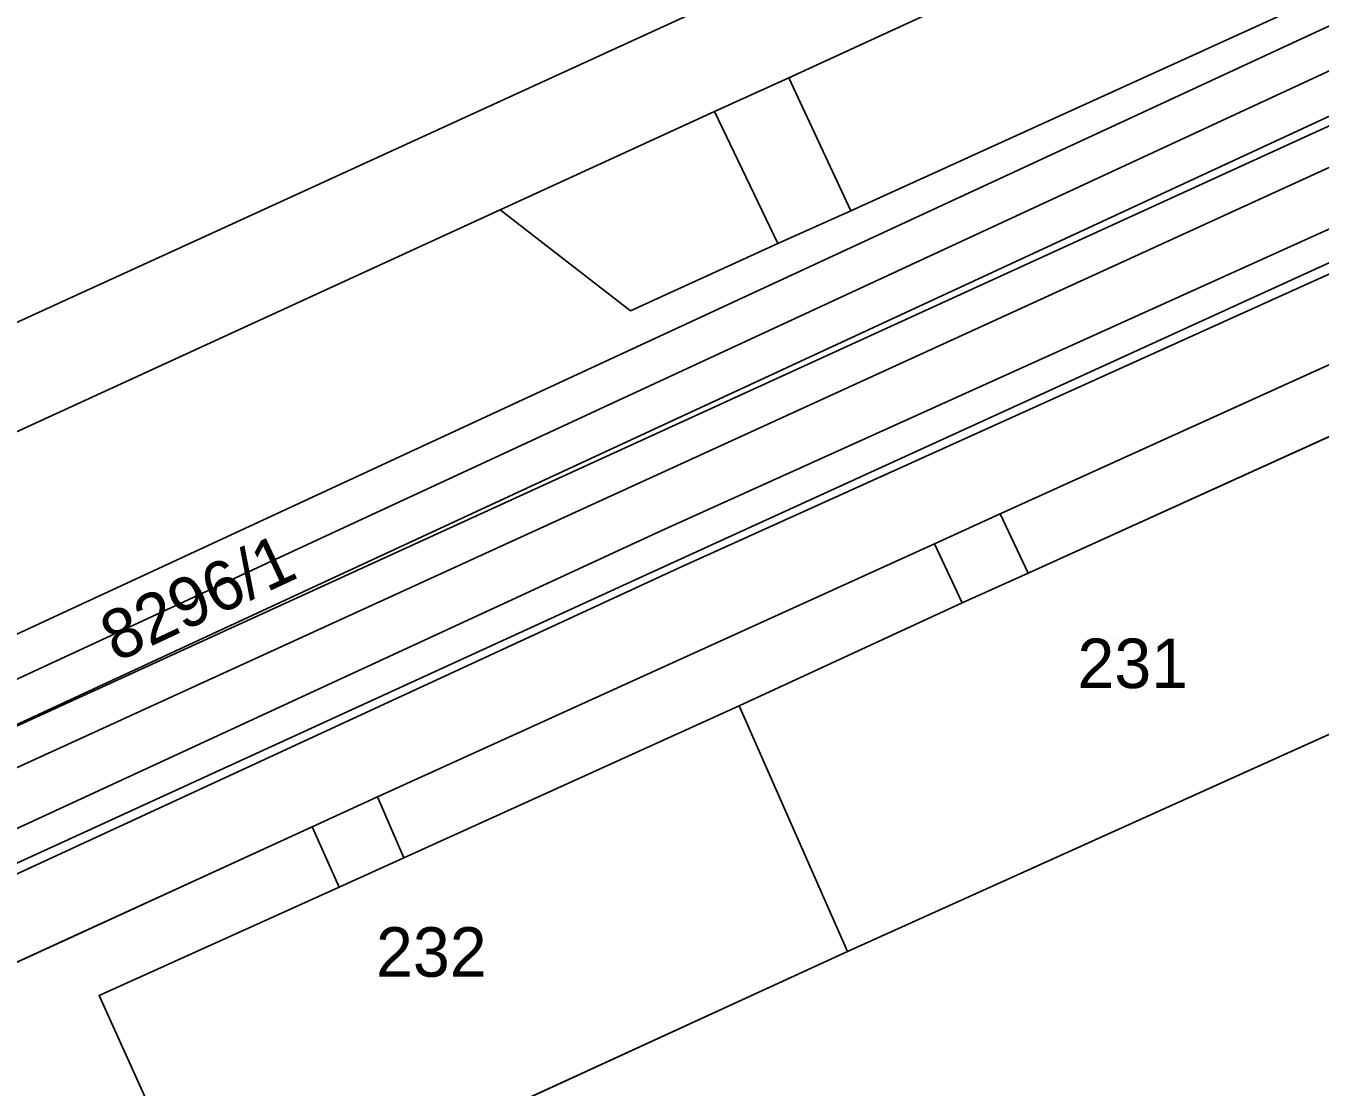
# Model space of a CAD drawing. Extents: x -264070 to -262271, y -1238894 to -1238141.
# Drawn here: x -263532.4 to -263480.2, y -1238438.9 to -1238396.1 of the extents above; entities that cross this region are included whole.
import ezdxf

# ---------------------------------------------------------------- set-up
doc = ezdxf.new("R2010")
doc.units = 0
for name, color, linetype in [('body_kn', 7, 'Continuous'), ('katuz_linie', 7, 'Continuous'), ('kladpar_druhypozemkov', 7, 'Continuous'), ('kladpar_hranice', 7, 'Continuous'), ('kladpar_parcelnecisla', 7, 'Continuous'), ('kladpar_plochy', 7, 'Continuous'), ('tarchy_linie', 7, 'Continuous'), ('zappar_hrandruhpozemk', 7, 'Continuous'), ('zuob_linie', 7, 'Continuous'), ('zuob_plochy', 7, 'Continuous')]:
    doc.layers.add(name, color=color, linetype=linetype)

msp = doc.modelspace()

# ---------------------------------------------------------------- linework, layer by layer
at = {"layer": 'body_kn'}
for p, q in [((-263501.63, -1238398.17), (-263501.63, -1238398.17)), ((-263504.63, -1238399.53), (-263504.63, -1238399.53)), ((-263504.63, -1238399.53), (-263504.63, -1238399.53)), ((-263513.28, -1238403.5), (-263513.28, -1238403.5)), ((-263499.13, -1238403.54), (-263499.13, -1238403.54)), ((-263499.13, -1238403.54), (-263499.13, -1238403.54)), ((-263524.87, -1238404.43), (-263524.87, -1238404.43)), ((-263502.07, -1238404.86), (-263502.07, -1238404.86)), ((-263508.02, -1238407.57), (-263508.02, -1238407.57)), ((-263493.11, -1238415.76), (-263493.11, -1238415.76)), ((-263493.11, -1238415.76), (-263493.11, -1238415.76)), ((-263506.75, -1238416.44), (-263506.75, -1238416.44)), ((-263495.75, -1238416.97), (-263495.75, -1238416.97)), ((-263495.75, -1238416.97), (-263495.75, -1238416.97)), ((-263506.06, -1238417.94), (-263506.06, -1238417.94)), ((-263507.21, -1238418.15), (-263507.21, -1238418.15)), ((-263491.98, -1238418.16), (-263491.98, -1238418.16)), ((-263494.64, -1238419.36), (-263494.64, -1238419.36)), ((-263503.63, -1238423.51), (-263503.63, -1238423.51)), ((-263518.23, -1238427.19), (-263518.23, -1238427.19)), ((-263518.23, -1238427.19), (-263518.23, -1238427.19)), ((-263520.86, -1238428.4), (-263520.86, -1238428.4)), ((-263520.86, -1238428.4), (-263520.86, -1238428.4)), ((-263517.17, -1238429.65), (-263517.17, -1238429.65)), ((-263517.17, -1238429.65), (-263517.17, -1238429.65)), ((-263519.77, -1238430.84), (-263519.77, -1238430.84)), ((-263499.27, -1238433.43), (-263499.27, -1238433.43)), ((-263529.46, -1238435.2), (-263529.46, -1238435.2))]:
    msp.add_line(p, q, dxfattribs=at)
at = {"layer": 'katuz_linie'}
msp.add_lwpolyline([(-263622.11, -1238448.88), (-263524.87, -1238404.43), (-263502.54, -1238394.19), (-263468.52, -1238378.6), (-263467.05, -1238377.92), (-263464.65, -1238376.78), (-263460.69, -1238376.7), (-263450.55, -1238372.11), (-263449.05, -1238375.25), (-263448.24, -1238376.95), (-263444.79, -1238375.86), (-263433.14, -1238370.43), (-263430.29, -1238369.1), (-263427.85, -1238367.96), (-263393.36, -1238351.8)], dxfattribs=at)
at = {"layer": 'kladpar_druhypozemkov'}
for p, q in [((-263525.79, -1238417.32), (-263525.79, -1238417.32)), ((-263488.36, -1238420.85), (-263488.36, -1238420.85)), ((-263516.11, -1238432.8), (-263516.11, -1238432.8))]:
    msp.add_line(p, q, dxfattribs=at)
at = {"layer": 'kladpar_hranice'}
msp.add_line((-263495.75, -1238416.97), (-263493.11, -1238415.76), dxfattribs=at)
for points in [[(-263622.11, -1238448.88), (-263524.87, -1238404.43), (-263502.54, -1238394.19), (-263468.52, -1238378.6), (-263467.05, -1238377.92), (-263464.65, -1238376.78), (-263460.69, -1238376.7), (-263450.55, -1238372.11), (-263449.05, -1238375.25), (-263448.24, -1238376.95), (-263447.6, -1238377.58), (-263446.38, -1238378.21), (-263445.22, -1238378.56), (-263432.12, -1238372.59), (-263370.5, -1238344.51)], [(-263393.39, -1238373.8), (-263400.64, -1238377.05), (-263402.96, -1238378.11), (-263409.73, -1238381.24), (-263417.07, -1238384.49), (-263419.5, -1238385.56), (-263426.69, -1238388.84), (-263428.02, -1238386.05), (-263431.45, -1238387.66), (-263438.05, -1238390.73), (-263440.52, -1238391.82), (-263451.66, -1238396.9), (-263468.15, -1238404.43), (-263470.58, -1238405.55), (-263493.11, -1238415.76), (-263495.75, -1238416.97), (-263518.23, -1238427.19), (-263520.86, -1238428.4), (-263537.75, -1238436.14)], [(-263493.11, -1238415.76), (-263470.58, -1238405.55), (-263468.15, -1238404.43), (-263451.66, -1238396.9), (-263450.61, -1238399.35), (-263426.11, -1238459), (-263424.74, -1238462.35), (-263423.38, -1238465.68), (-263422.04, -1238468.97), (-263420.59, -1238472.47), (-263419.19, -1238475.61), (-263423.39, -1238477.55), (-263433.56, -1238482.16), (-263502.82, -1238513.93), (-263509.7, -1238497.82), (-263513.9, -1238488.48), (-263515.71, -1238484.44), (-263521.05, -1238472.6), (-263524.45, -1238465.05), (-263526.3, -1238460.78), (-263530.53, -1238451.52), (-263534.06, -1238443.82)], [(-263474.15, -1238422.1), (-263452.92, -1238412.46), (-263454.93, -1238407.94), (-263450.88, -1238406.06), (-263453.34, -1238400.63), (-263467.07, -1238406.77), (-263469.48, -1238407.89), (-263478.58, -1238412.08), (-263491.98, -1238418.16), (-263494.64, -1238419.36), (-263503.63, -1238423.51), (-263517.17, -1238429.65), (-263519.77, -1238430.84), (-263529.46, -1238435.2), (-263527, -1238440.63), (-263526.85, -1238441.05), (-263525.15, -1238444.9), (-263525, -1238445.24), (-263499.27, -1238433.43), (-263474.15, -1238422.1)], [(-263478.58, -1238412.08), (-263474.15, -1238422.1), (-263499.27, -1238433.43), (-263503.63, -1238423.51), (-263494.64, -1238419.36), (-263491.98, -1238418.16), (-263478.58, -1238412.08)], [(-263537.75, -1238436.14), (-263520.86, -1238428.4), (-263518.23, -1238427.19), (-263495.75, -1238416.97)], [(-263517.17, -1238429.65), (-263503.63, -1238423.51), (-263499.27, -1238433.43), (-263525, -1238445.24), (-263525.15, -1238444.9), (-263526.85, -1238441.05), (-263527, -1238440.63), (-263529.46, -1238435.2), (-263519.77, -1238430.84), (-263517.17, -1238429.65)]]:
    msp.add_lwpolyline(points, dxfattribs=at)
at = {"layer": 'kladpar_plochy'}
for p, q in [((-263493.11, -1238415.76), (-263470.58, -1238405.55)), ((-263478.58, -1238412.08), (-263491.98, -1238418.16)), ((-263495.75, -1238416.97), (-263493.11, -1238415.76)), ((-263518.23, -1238427.19), (-263495.75, -1238416.97)), ((-263491.98, -1238418.16), (-263494.64, -1238419.36)), ((-263494.64, -1238419.36), (-263503.63, -1238423.51)), ((-263499.27, -1238433.43), (-263474.15, -1238422.1)), ((-263503.63, -1238423.51), (-263517.17, -1238429.65)), ((-263520.86, -1238428.4), (-263518.23, -1238427.19)), ((-263537.75, -1238436.14), (-263520.86, -1238428.4)), ((-263517.17, -1238429.65), (-263519.77, -1238430.84)), ((-263519.77, -1238430.84), (-263529.46, -1238435.2)), ((-263525, -1238445.24), (-263499.27, -1238433.43)), ((-263529.46, -1238435.2), (-263527, -1238440.63))]:
    msp.add_line(p, q, dxfattribs=at)
for points in [[(-263622.11, -1238448.88), (-263524.87, -1238404.43), (-263502.54, -1238394.19), (-263468.52, -1238378.6), (-263467.05, -1238377.92), (-263464.65, -1238376.78), (-263460.69, -1238376.7), (-263450.55, -1238372.11), (-263449.05, -1238375.25), (-263448.24, -1238376.95), (-263447.6, -1238377.58), (-263446.38, -1238378.21), (-263445.22, -1238378.56), (-263432.12, -1238372.59), (-263370.5, -1238344.51)], [(-263393.39, -1238373.8), (-263400.64, -1238377.05), (-263402.96, -1238378.11), (-263409.73, -1238381.24), (-263417.07, -1238384.49), (-263419.5, -1238385.56), (-263426.69, -1238388.84), (-263428.02, -1238386.05), (-263431.45, -1238387.66), (-263438.05, -1238390.73), (-263440.52, -1238391.82), (-263451.66, -1238396.9), (-263468.15, -1238404.43), (-263470.58, -1238405.55), (-263493.11, -1238415.76), (-263495.75, -1238416.97), (-263518.23, -1238427.19), (-263520.86, -1238428.4), (-263537.75, -1238436.14)]]:
    msp.add_lwpolyline(points, dxfattribs=at)
for points in [[(-263478.58, -1238412.08), (-263474.15, -1238422.1), (-263499.27, -1238433.43), (-263503.63, -1238423.51), (-263494.64, -1238419.36), (-263491.98, -1238418.16)], [(-263517.17, -1238429.65), (-263503.63, -1238423.51), (-263499.27, -1238433.43), (-263525, -1238445.24), (-263525.15, -1238444.9), (-263526.85, -1238441.05), (-263527, -1238440.63), (-263529.46, -1238435.2), (-263519.77, -1238430.84)]]:
    msp.add_lwpolyline(points, close=True, dxfattribs=at)
at = {"layer": 'tarchy_linie'}
for points in [[(-264057.8, -1238661.22), (-263991.75, -1238634.81), (-263953.59, -1238615.83), (-263902.45, -1238592.17), (-263894.88, -1238589.22), (-263890.52, -1238587.61), (-263805.72, -1238548.49), (-263694.23, -1238497.41), (-263693.7, -1238498.42), (-263678.65, -1238491.83), (-263679.23, -1238490.22), (-263678.17, -1238489.62), (-263617.23, -1238461.76), (-263560.94, -1238435.5), (-263453.59, -1238385.71), (-263376.05, -1238350.16), (-263329.88, -1238328.77)], [(-264056.86, -1238661.79), (-263955.03, -1238615.7), (-263902.06, -1238590.93), (-263806.02, -1238547.49), (-263797.07, -1238543.46), (-263795.62, -1238546.45), (-263792.71, -1238545.26), (-263745.75, -1238523.77), (-263687.85, -1238496.76), (-263647.2, -1238478.29), (-263550.85, -1238434.28), (-263455.49, -1238390.65), (-263404.28, -1238367.05), (-263358.16, -1238345.65), (-263328.12, -1238332.27)], [(-263932.09, -1238607.52), (-263895.89, -1238591.28), (-263861.61, -1238576.56), (-263827.46, -1238561.85), (-263793.34, -1238547.55), (-263780.97, -1238541.82), (-263758.17, -1238531.52), (-263719.48, -1238513.81), (-263691.77, -1238500.91), (-263677.76, -1238494.67), (-263636.19, -1238475.69), (-263619.38, -1238467.98), (-263592.72, -1238455.89), (-263548.26, -1238435.63), (-263506.75, -1238416.44), (-263445.05, -1238388.54), (-263419.8, -1238377.15), (-263374.36, -1238356.49), (-263352.57, -1238346.28), (-263328.15, -1238332.21)], [(-263375.34, -1238351.65), (-263452.9, -1238387.21), (-263542.41, -1238428.73), (-263456.13, -1238389.25), (-263404.92, -1238365.65), (-263358.81, -1238344.25)], [(-263561.63, -1238434), (-263454.28, -1238384.21), (-263378.2, -1238349.33)], [(-263373.68, -1238357.99), (-263419.12, -1238378.65), (-263444.37, -1238390.04), (-263506.06, -1238417.94), (-263546.1, -1238436.46)]]:
    msp.add_lwpolyline(points, dxfattribs=at)
at = {"layer": 'zappar_hrandruhpozemk'}
for p, q in [((-263463.2, -1238380.46), (-263501.63, -1238398.17)), ((-263499.13, -1238403.54), (-263479.84, -1238394.75)), ((-263501.63, -1238398.17), (-263499.13, -1238403.54)), ((-263504.63, -1238399.53), (-263502.07, -1238404.86)), ((-263468.2, -1238400.3), (-263507.21, -1238418.15)), ((-263493.11, -1238415.76), (-263491.98, -1238418.16)), ((-263495.75, -1238416.97), (-263494.64, -1238419.36)), ((-263518.23, -1238427.19), (-263517.17, -1238429.65)), ((-263520.86, -1238428.4), (-263519.77, -1238430.84))]:
    msp.add_line(p, q, dxfattribs=at)
for points in [[(-263501.63, -1238398.17), (-263504.63, -1238399.53), (-263513.28, -1238403.5)], [(-263565.75, -1238434.26), (-263545.19, -1238424.91), (-263544.84, -1238417.98), (-263513.28, -1238403.5), (-263508.02, -1238407.57), (-263502.07, -1238404.86), (-263499.13, -1238403.54)], [(-263507.21, -1238418.15), (-263542.3, -1238434.22), (-263543.05, -1238435.12), (-263543.45, -1238436.3), (-263543.49, -1238437.33), (-263542.86, -1238438.6)]]:
    msp.add_lwpolyline(points, dxfattribs=at)
at = {"layer": 'zuob_linie'}
msp.add_lwpolyline([(-263622.11, -1238448.88), (-263524.87, -1238404.43), (-263502.54, -1238394.19), (-263468.52, -1238378.6), (-263467.05, -1238377.92), (-263464.65, -1238376.78), (-263460.69, -1238376.7), (-263450.55, -1238372.11), (-263449.05, -1238375.25), (-263448.24, -1238376.95), (-263444.79, -1238375.86), (-263433.14, -1238370.43), (-263430.29, -1238369.1), (-263427.85, -1238367.96), (-263393.36, -1238351.8)], dxfattribs=at)
at = {"layer": 'zuob_plochy'}
msp.add_lwpolyline([(-263622.11, -1238448.88), (-263524.87, -1238404.43), (-263502.54, -1238394.19), (-263468.52, -1238378.6), (-263467.05, -1238377.92), (-263464.65, -1238376.78), (-263460.69, -1238376.7), (-263450.55, -1238372.11), (-263449.05, -1238375.25), (-263448.24, -1238376.95), (-263444.79, -1238375.86), (-263433.14, -1238370.43), (-263430.29, -1238369.1), (-263427.85, -1238367.96), (-263393.36, -1238351.8)], dxfattribs=at)

# ---------------------------------------------------------------- texts
at = {"layer": 'kladpar_parcelnecisla'}
msp.add_text('8296/1', height=2, rotation=25, dxfattribs=at).set_placement((-263528.769, -1238421.773))
for s, p in [('231', (-263489.989, -1238422.8)), ('232', (-263518.285, -1238434.45))]:
    msp.add_text(s, height=2, dxfattribs=at).set_placement(p)

doc.saveas('drawing.dxf')
